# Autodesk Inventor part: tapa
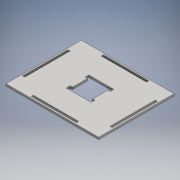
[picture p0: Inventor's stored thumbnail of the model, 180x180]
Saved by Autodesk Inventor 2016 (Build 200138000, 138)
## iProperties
Created: 2016-06
Part Number: tapa
Material: Genérico
Document SubType Name: Modeling
Designer: adm
Density: 1 g/cm^3
Appearance: Valor por defecto
Author: adm
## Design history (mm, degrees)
sketch "Boceto1"
  geometry: L1 (-61, -30)-(-58, -30); L2 (-31.5, -45)-(-31.5, -48); L3 (-61, -30)-(-61, 30); L4 (-61, 30)-(-58, 30); L5 (-58, 30)-(-58, -30); L6 (-31.5, -45)-(28.5, -45); L7 (28.5, -45)-(28.5, -48); L8 (28.5, -48)-(-31.5, -48); L9 (-31.5, 48)-(-31.5, 45); L10 (-63, 50)-(-63, -50); L11 (-63, -50)-(60, -50); L12 (28.5, 45)-(-31.5, 45); L13 (-31.5, 48)-(28.5, 48); L14 (-63, -50)-(60, 50); L15 (60, 50)-(-63, 50); L16 (60, -50)-(-63, 50); L17 (60, -50)-(60, 50); L18 (28.5, 48)-(28.5, 45); L19 (55, -30)-(55, 30); L20 (55, 30)-(58, 30); L21 (58, 30)-(58, -30); L22 (55, -30)-(58, -30); L23 (-18, 15)-(15, 15); L24 (15, -15)-(-18, -15); L25 (-18, 15)-(15, -15); L26 (15, 15)-(-18, -15); L27 (-15, 10)-(-15, -10); L28 (12, -10)-(12, 10); L29 (-18, -15)-(-18, -10); L30 (-18, 10)-(-18, 15); L31 (15, 15)-(15, 10); L32 (15, -10)-(15, -15); L33 (15, 10)-(12, 10); L34 (-15, 10)-(-18, 10); L35 (-18, -10)-(-15, -10); L36 (12, -10)-(15, -10); 2 further points
  constraints: 72 end point, 16 parallel, 7 perpendicular, 4 midpoint, 2 horizontal
  dimensions: "d0" = 100 distance of L14.end L11.end; "d1" = 123 distance of L14.end L10.start; "d2" = 33 distance of L24.start L24.end; "d3" = 30 distance of L23.end L24.start; "d7" = 5 distance between parallel lines of L34 L23; "d8" = 5 distance between parallel lines of L33 L23; "d9" = 5 distance between parallel lines of L24 L36; "d10" = 5 distance between parallel lines of L35 L24; "d11" = 31.5 distance between parallel lines of L2 L10; "d12" = 20 distance between parallel lines of L11 L1; "d13" = 2 distance between parallel lines of L3 L10; "d14" = 3 distance of L3.end L4.end; "d15" = 2 distance between parallel lines of L21 L17; "d17" = 3 distance between parallel lines of L19 L21; "d19" = 31.5 distance between parallel lines of L10 L9; "d21" = 60 distance between parallel lines of L18 L9
extrude "Extrusión1" new body sketch "Boceto1" distance "d5" = 3; taper "d6" = 0 deg
node "Sólido1"
other parameters: "d4" = 3
